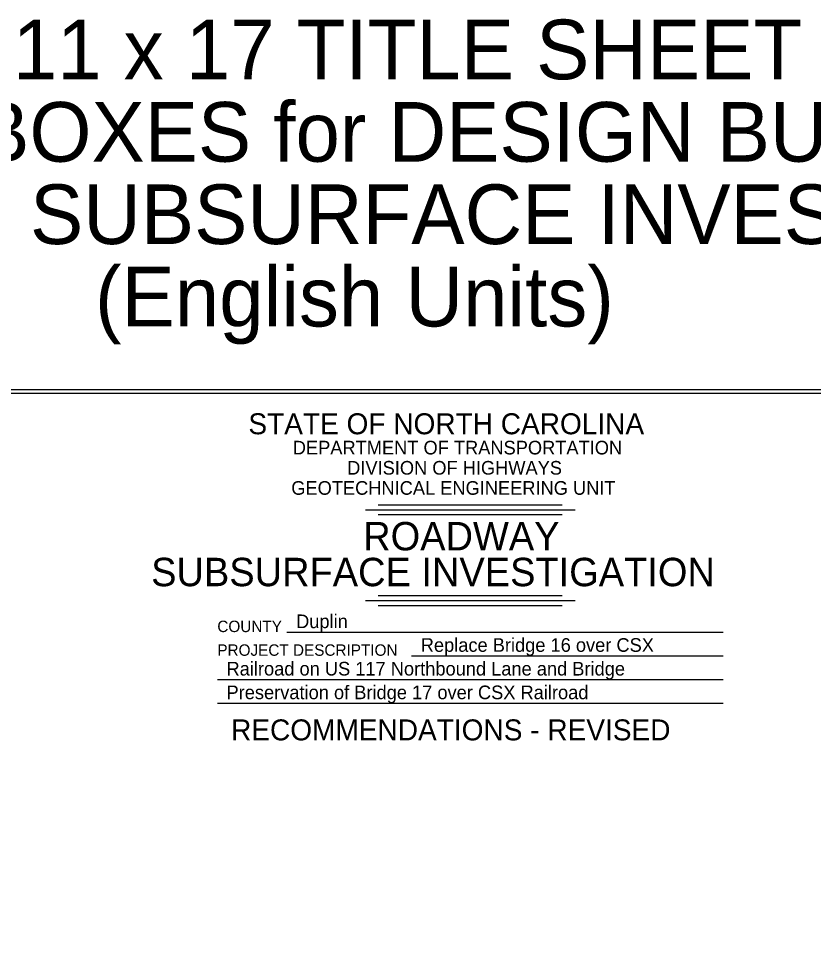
# Model space of a CAD drawing. Extents: x 265553 to 275568, y 168312 to 173522.
# Drawn here: x 273079 to 273778, y 172697 to 173522 of the extents above; entities that cross this region are included whole.
import ezdxf

# ---------------------------------------------------------------- set-up
doc = ezdxf.new("R2010")
doc.units = 0
for name, color, linetype in [('Geotech Sheets and Borders Cell', 7, 'Continuous'), ('Scratch_Level_2', 7, 'Continuous'), ('Sheet Plot Border Inside CELL', 7, 'Continuous')]:
    doc.layers.add(name, color=color, linetype=linetype)

msp = doc.modelspace()

# ---------------------------------------------------------------- linework, layer by layer
at = {"layer": 'Geotech Sheets and Borders Cell'}
for p, q in [((273383.9, 173089.9), (273568.35, 173089.9)), ((273395.25, 173094.22), (273557, 173094.22)), ((273395.25, 173085.59), (273557, 173085.59)), ((273395.25, 173014.39), (273557, 173014.39)), ((273383.9, 173010.08), (273568.35, 173010.08)), ((273395.25, 173005.77), (273557, 173005.77)), ((273314.89, 172982.24), (273698.59, 172982.24)), ((273424.56, 172961.39), (273698.59, 172961.39)), ((273253.66, 172940.55), (273698.59, 172940.55)), ((273253.66, 172919.7), (273698.59, 172919.7))]:
    msp.add_line(p, q, dxfattribs=at)
msp.add_lwpolyline([(272700.69, 173192.58), (274200.69, 173192.58), (274200.69, 172142.58), (272700.69, 172142.58)], close=True, dxfattribs=at)
at = {"layer": 'Sheet Plot Border Inside CELL'}
msp.add_lwpolyline([(272545.53, 172139.74), (274213.19, 172139.74), (274213.19, 173195.41), (272545.53, 173195.41)], close=True, dxfattribs=at)

# ---------------------------------------------------------------- texts
at = {"layer": 'Geotech Sheets and Borders Cell'}
for s, height, p in [('STATE OF NORTH CAROLINA', 18.4505, (273280.96, 173156.34)), ('DEPARTMENT OF TRANSPORTATION', 12, (273320.04, 173138.58)), ('DIVISION OF HIGHWAYS', 12, (273367.87, 173120.83)), ('GEOTECHNICAL ENGINEERING UNIT', 12, (273318.68, 173103.08)), ('ROADWAY', 25, (273381.97, 173054.17)), ('SUBSURFACE INVESTIGATION', 25, (273195.42, 173022.63)), ('Duplin', 12, (273322.95, 172985.73)), ('COUNTY', 10.064, (273253.66, 172982.24)), ('Replace Bridge 16 over CSX ', 12, (273432.62, 172964.89)), ('PROJECT DESCRIPTION', 10.0637, (273253.66, 172961.39)), ('Railroad on US 117 Northbound Lane and Bridge ', 12, (273261.72, 172944.04)), ('Preservation of Bridge 17 over CSX Railroad', 12, (273261.72, 172923.2)), ('RECOMMENDATIONS - REVISED', 18.4505, (273265.74, 172886.95))]:
    msp.add_text(s, height=height, dxfattribs=at).set_placement(p)
at = {"layer": 'Scratch_Level_2'}
for s, p in [('11 x 17 TITLE SHEET', (273073.68, 173468.71)), ('w/ 2 SEAL BOXES for DESIGN BUILD', (272694.2, 173396.21)), ('ROADWAY SUBSURFACE INVESTIGATION', (272706.6, 173323.71)), ('(English Units)', (273146.03, 173251.21))]:
    msp.add_text(s, height=52.5002, dxfattribs=at).set_placement(p)

doc.saveas('drawing.dxf')
